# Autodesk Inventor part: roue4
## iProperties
Author: Administrateur
Shininess: 20.0
PropertySet Name: _Private Model Information
Length Units: 11269
Angle Units: 11283
Time Units: 11279
Mass Units: 11290
Length Display Precision: 3
Angle Display Precision: 2
Compacted: False
Created: 2001-04
Part Number: roue4
Material: Par défaut
Document SubType Name: Modélisation
Designer: Administrateur
Control State: 0
Master: False
Checked Out: False
PropertySet Name: Design Tracking Control
Density: 0.0
Volumn: 0.0
Area: 0.0
PropertySet Name: Model Information
